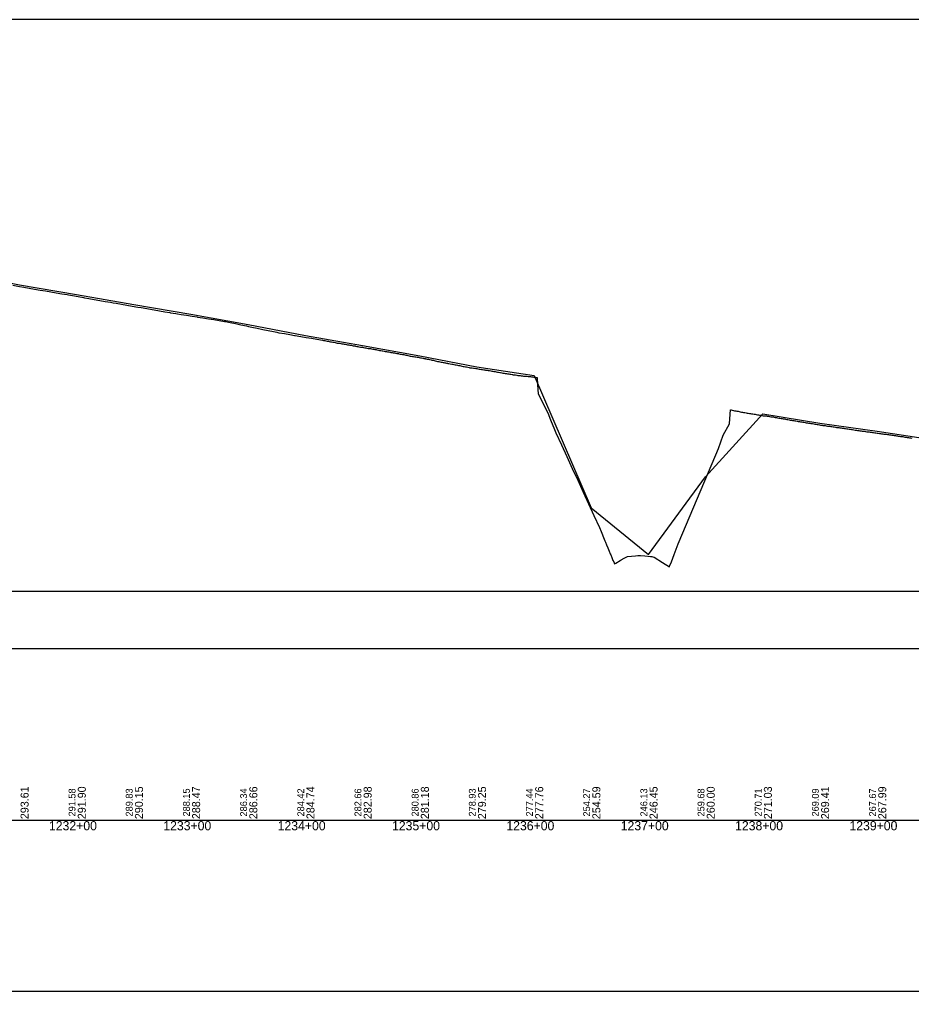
# Model space of a CAD drawing. Extents: x -3627 to 47473, y 2850 to 4350.
# Drawn here: x 10527 to 11307, y 2850 to 3700 of the extents above; entities that cross this region are included whole.
import ezdxf

# ---------------------------------------------------------------- set-up
doc = ezdxf.new("R2010")
doc.units = 0
for name, color, linetype in [('RD_DDB_Profile_EX', 7, 'Continuous'), ('RD_DDB_Profile_PR', 7, 'Continuous'), ('RD_DDB_StaTX', 7, 'Continuous'), ('RD_DDB_StripGrade', 7, 'Continuous'), ('RD_GPK_Profile_Cell', 7, 'Continuous'), ('RD_SHT_ShtClip', 7, 'Continuous')]:
    doc.layers.add(name, color=color, linetype=linetype)

msp = doc.modelspace()

# ---------------------------------------------------------------- linework, layer by layer
at = {"layer": 'RD_DDB_Profile_EX'}
for points in [[(10521.543546, 3467.5408), (10527.331218, 3466.473835), (10531.042498, 3465.8499), (10535.791975, 3465.048495), (10540.541451, 3464.24416), (10545.394843, 3463.41546), (10550.040404, 3462.623205), (10554.78988, 3461.81021), (10559.539357, 3460.99421), (10564.288833, 3460.1752), (10569.038309, 3459.353185), (10570.21671, 3459.14425), (10573.787786, 3458.523185), (10578.537262, 3457.694075), (10583.286738, 3456.86186), (10584.337263, 3456.67577), (10588.036215, 3456.02534), (10592.785691, 3455.18704), (10597.535167, 3454.345585), (10602.284644, 3453.50099), (10607.03412, 3452.65325), (10609.280141, 3452.25028), (10611.783596, 3451.824845), (10616.533073, 3451.014475), (10621.282549, 3450.200865), (10626.032025, 3449.384015), (10630.781502, 3448.563925), (10633.757415, 3448.048045), (10635.530978, 3447.7406), (10640.280455, 3446.91405)], [(10640.280455, 3446.91405), (10645.029931, 3446.084265), (10649.779407, 3445.251245), (10654.528884, 3444.414995), (10658.796669, 3443.65973), (10659.27836, 3443.58503), (10664.027836, 3442.845015), (10665.62232, 3442.5954), (10668.777313, 3442.09581), (10673.526789, 3441.341925), (10678.276265, 3440.58624), (10682.712889, 3439.86768), (10683.025742, 3439.817665), (10687.775218, 3439.057435), (10692.524694, 3438.296295), (10697.274171, 3437.53424), (10702.023647, 3436.771275), (10706.773123, 3436.007405), (10707.536259, 3435.87992), (10711.5226, 3435.037695), (10716.272076, 3434.033025), (10721.021552, 3433.02714), (10725.771029, 3432.020045), (10727.701013, 3431.648155), (10730.520505, 3431.05129), (10735.269982, 3430.04314), (10740.019458, 3429.03227), (10744.768934, 3428.01868), (10749.518411, 3427.00238), (10752.414609, 3426.418435), (10754.267887, 3426.09926), (10759.017363, 3425.277585), (10763.76684, 3424.452205), (10767.862399, 3423.713405), (10768.516316, 3423.602885), (10773.265792, 3422.797305), (10778.015269, 3421.98886), (10782.764745, 3421.17755), (10787.514221, 3420.36338), (10792.30311, 3419.57975), (10793.299339, 3419.285795), (10794.299228, 3419.14256), (10795.303154, 3418.943025), (10796.30302, 3418.74236), (10797.299199, 3418.58722), (10798.299138, 3418.43557), (10799.302349, 3418.18956), (10800.302281, 3417.99978), (10801.306182, 3417.80405), (10801.76265, 3417.758265), (10802.296945, 3417.704175), (10803.300912, 3417.483735), (10804.300165, 3417.34362), (10805.299063, 3417.053465), (10806.512127, 3416.93618), (10807.293775, 3416.84868), (10808.296695, 3416.689405), (10809.295635, 3416.499), (10810.299296, 3416.34801), (10811.289227, 3416.143485), (10812.292583, 3415.98803), (10813.291601, 3415.792745), (10814.293861, 3415.587365), (10815.29287, 3415.44605), (10816.287852, 3415.238785), (10817.285493, 3415.13517), (10818.288555, 3414.937095), (10819.28689, 3414.698905), (10820.236153, 3414.553075), (10820.760556, 3414.47179), (10821.232904, 3414.39124), (10822.230999, 3414.144775), (10823.222926, 3413.95443), (10824.221468, 3413.84666), (10825.510032, 3413.58003), (10826.221282, 3413.40868), (10827.21984, 3413.303775), (10828.219735, 3413.15324), (10829.225637, 3413.00416), (10830.259509, 3412.83919), (10831.2229, 3412.652015), (10832.215968, 3412.415745), (10833.215832, 3412.255615), (10834.221707, 3412.15596), (10835.214283, 3411.920275), (10836.219608, 3411.81587), (10837.219989, 3411.568015), (10838.218037, 3411.41629), (10839.217698, 3411.3046), (10839.758461, 3411.168325), (10840.215748, 3411.061815), (10841.215574, 3410.736265), (10842.215949, 3410.633465), (10843.213991, 3410.562915), (10844.507938, 3410.30062), (10845.219663, 3410.122675), (10846.212225, 3410.01766), (10847.217354, 3409.7752), (10848.209908, 3409.6658), (10849.257414, 3409.500895), (10850.215579, 3409.36089)], [(10850.215579, 3409.36089), (10851.208125, 3409.159955), (10852.213972, 3408.91263), (10853.213797, 3408.772075), (10854.211838, 3408.60583), (10855.211503, 3408.364145), (10856.204026, 3408.26264), (10857.209885, 3408.002185), (10858.20972, 3407.852405), (10858.756367, 3407.768325), (10859.207769, 3407.69868), (10860.208089, 3407.40217), (10861.213499, 3407.253535), (10862.20598, 3407.097785), (10863.505843, 3406.92422), (10864.203749, 3406.789215), (10865.204045, 3406.55249), (10865.999784, 3406.4476), (10867.057171, 3406.27399), (10868.255319, 3405.95116), (10868.979874, 3405.71299), (10869.981382, 3405.658365), (10871.057632, 3405.35229), (10871.977767, 3405.263525), (10873.061131, 3405.10046), (10874.065337, 3404.92293), (10874.981471, 3404.696475), (10876.064321, 3404.638615), (10876.977635, 3404.367665), (10877.972417, 3404.16866), (10878.973787, 3404.00678), (10880.062261, 3403.752835), (10880.970699, 3403.61878), (10881.972038, 3403.456255), (10882.503748, 3403.269245), (10883.063689, 3403.10206), (10883.968386, 3402.96807), (10885.061111, 3402.83864), (10885.96452, 3402.56961), (10887.253225, 3402.341515), (10887.960651, 3402.205725), (10889.056201, 3401.975375), (10889.957593, 3401.70641), (10890.958873, 3401.541925), (10892.055873, 3401.23155), (10892.955822, 3401.05243), (10893.95595, 3400.855115), (10895.057622, 3400.63565), (10896.05179, 3400.43008), (10896.953578, 3400.25052), (10897.954863, 3400.090495), (10898.43082, 3400), (10899.200461, 3399.766405), (10899.980789, 3399.649735), (10900.756284, 3399.49272), (10901.537873, 3399.37586), (10901.947913, 3399.288625), (10902.942719, 3399.16792), (10903.944035, 3398.882175), (10905.321318, 3398.572545), (10906.289417, 3398.434385), (10907.285695, 3398.18517), (10908.286228, 3397.993515), (10909.290089, 3397.890085), (10910.286909, 3397.696015), (10911.286863, 3397.4883), (10912.291126, 3397.30064), (10913.287248, 3397.09546), (10914.287728, 3396.80391), (10915.283841, 3396.615925), (10915.750083, 3396.570505), (10916.288006, 3396.487835), (10917.287768, 3396.25202), (10918.284402, 3396.145925), (10919.287844, 3395.95293), (10920.499559, 3395.674865), (10921.284159, 3395.517355), (10922.288121, 3395.367915), (10923.279311, 3395.25027), (10924.284325, 3395.157155), (10925.287587, 3395.00146), (10926.279366, 3394.83922), (10927.283602, 3394.65242), (10928.287439, 3394.49617), (10929.283221, 3394.31484), (10930.282738, 3394.12304), (10931.286477, 3393.97289), (10932.282174, 3393.80914), (10933.282317, 3393.710355), (10934.278008, 3393.50955), (10934.747988, 3393.46299), (10935.281708, 3393.402845), (10936.281067, 3393.24738), (10937.277375, 3393.059105), (10938.280349, 3392.921685), (10939.497465, 3392.70068), (10940.275954, 3392.490415), (10941.279549, 3392.426855), (10942.271456, 3392.23316), (10943.275053, 3392.08234), (10944.277978, 3391.956635)], [(10944.277978, 3391.956635), (10945.27047, 3391.68115), (10946.273334, 3391.574015), (10947.276886, 3391.422945), (10948.125354, 3391.223745), (10949.124194, 3391.036385), (10950.122287, 3390.855175), (10951.148796, 3390.59418), (10952.148343, 3390.44546), (10953.142979, 3390.32913), (10954.142482, 3390.09315), (10955.141247, 3389.994275), (10956.140658, 3389.875385), (10957.148192, 3389.713985), (10958.147617, 3389.57145), (10958.49537, 3389.501975), (10959.146274, 3389.372215), (10960.145539, 3389.265875), (10961.139915, 3389.1315), (10962.146749, 3388.939905), (10963.244846, 3388.77369), (10964.145717, 3388.676975), (10965.14415, 3388.54154), (10966.143276, 3388.39177), (10967.149238, 3388.26466), (10968.148342, 3388.222045), (10969.146607, 3388.136565), (10970.142673, 3388.010195), (10971.140938, 3387.99669), (10972.147425, 3387.81277), (10973.145623, 3387.75551), (10974.14443, 3387.69941), (10975.142528, 3387.48992), (10976.142609, 3387.381435), (10977.148226, 3387.203235), (10977.493275, 3387.1688), (10978.142782, 3387.104045), (10979.140709, 3387.06081), (10979.998327, 3387.024545), (10980.478464, 3380.58499), (10980.995674, 3372.54904), (10982.242752, 3370.042175), (10986.992228, 3360.49365), (10989.273855, 3355.906035), (10991.741705, 3349.777605), (10995.093873, 3341.451325), (10996.491181, 3338.414105), (11001.240657, 3328.08981), (11005.990134, 3317.764805), (11010.73961, 3307.439125), (11015.489086, 3297.112795), (11020.238563, 3286.78585), (11024.988039, 3276.45831), (11029.737515, 3266.130215), (11034.486992, 3255.801585), (11036.158402, 3252.166615), (11038.785117, 3245.509115), (11039.236468, 3244.248405), (11039.723685, 3242.888265), (11040.757161, 3240.529295), (11041.868532, 3238.03651), (11043.09915, 3235.14413), (11043.985944, 3232.84878), (11044.353961, 3231.89664), (11045.337396, 3229.568125), (11046.313644, 3226.949935), (11046.96272, 3225.75562), (11047.750403, 3224.08031), (11048.735421, 3224.659325), (11052.713079, 3226.998465), (11053.484897, 3227.4145), (11056.083854, 3228.815255), (11058.928951, 3230.36871), (11062.518094, 3230.696995), (11066.057082, 3231.0213), (11068.206228, 3231.208645), (11070.404375, 3231.419235), (11074.150154, 3230.998715), (11079.0208, 3230.45052), (11080.237702, 3230.313655), (11081.180516, 3230.20771), (11082.440301, 3229.869885), (11089.630611, 3225.29527), (11095.721485, 3221.48838), (11096.089507, 3222.43014), (11097.446264, 3225.824595), (11098.664693, 3229.068585), (11099.788999, 3232.04427), (11103.424789, 3241.514595), (11104.174874, 3243.540475), (11138.549471, 3324.95213), (11142.802066, 3336.407525), (11148.165449, 3346.339715), (11148.874291, 3354.928305), (11149.230024, 3358.743785), (11149.561851, 3358.646965), (11150.691356, 3358.433315), (11151.690668, 3358.183495), (11152.693441, 3357.896705), (11153.684135, 3357.706675), (11154.688151, 3357.576625)], [(11154.688151, 3357.576625), (11155.687467, 3357.39685), (11156.689704, 3357.240055), (11157.684389, 3356.89625), (11158.684944, 3356.64655), (11159.687186, 3356.533165), (11160.553298, 3356.35998), (11161.682409, 3356.24625), (11162.681208, 3356.009885), (11163.551638, 3355.83608), (11164.678636, 3355.676225), (11165.678671, 3355.50288), (11166.681439, 3355.372405), (11167.548557, 3355.24261), (11168.675414, 3355.015495), (11169.675456, 3354.92924), (11170.546896, 3354.79856), (11171.672856, 3354.51505), (11172.671673, 3354.315525), (11173.675664, 3354.26531), (11174.543814, 3354.048455), (11175.669112, 3353.95206), (11176.668449, 3353.71309), (11177.672436, 3353.45219), (11178.540733, 3353.495895), (11178.863948, 3353.479455), (11179.71095, 3353.30824), (11180.568666, 3353.265185), (11181.303162, 3353.11465), (11182.307317, 3353.01467), (11183.298534, 3352.7), (11184.301413, 3352.585265), (11185.305571, 3352.49262), (11186.304188, 3352.4), (11187.300959, 3352.170315), (11188.299591, 3352.027495), (11189.301702, 3351.88496), (11190.298487, 3351.785035), (11191.297115, 3351.492435), (11192.301285, 3351.362105), (11193.299912, 3351.15), (11194.295396, 3351.05), (11195.299569, 3350.84237), (11196.298201, 3350.634565), (11197.301037, 3350.484555), (11198.292897, 3350.32665), (11199.295725, 3350.18442), (11200.299907, 3349.942195), (11201.298534, 3349.718415), (11202.387926, 3349.57648), (11203.388252, 3349.37625), (11204.390252, 3349.31841), (11205.393751, 3349.152665), (11206.386102, 3348.902535), (11207.38869, 3348.73425), (11208.389038, 3348.568185), (11209.392536, 3348.426165), (11210.386531, 3348.23426), (11211.386894, 3348.034105), (11212.39039, 3347.88412), (11213.381839, 3347.760325), (11214.385333, 3347.55244), (11215.388825, 3347.41041), (11216.387705, 3347.252075), (11217.38318, 3347.068315), (11218.383597, 3346.90999), (11219.385564, 3346.76807), (11220.229469, 3346.6), (11220.870179, 3346.56812), (11221.869667, 3346.367795), (11222.867744, 3346.17563), (11223.867242, 3345.97538), (11224.866753, 3345.866835), (11225.864811, 3345.69982), (11226.865155, 3345.51628), (11227.864696, 3345.38297), (11228.866784, 3345.224505), (11229.866321, 3345.07425), (11230.865871, 3344.906645), (11231.8639, 3344.815015), (11232.863462, 3344.60583), (11233.871105, 3344.432075), (11234.869105, 3344.33192), (11235.868687, 3344.222615), (11236.868283, 3344.08156), (11237.870234, 3343.940795), (11238.869826, 3343.790705), (11239.870342, 3343.690635), (11240.868312, 3343.53111), (11241.867936, 3343.34046), (11242.827964, 3343.15), (11243.828254, 3343.059665), (11244.826916, 3342.880555), (11245.825578, 3342.8), (11246.82424, 3342.60984), (11247.826118, 3342.5), (11248.826444, 3342.320305), (11249.825104, 3342.190045), (11250.823764, 3342.05), (11251.822424, 3341.91007), (11252.821083, 3341.779745)], [(11252.821083, 3341.779745), (11253.828223, 3341.620525), (11254.826883, 3341.46032), (11255.824439, 3341.35), (11256.827306, 3341.2), (11258.271562, 3340.989525), (11259.271035, 3340.8), (11260.270507, 3340.66059), (11261.26998, 3340.489355), (11262.269452, 3340.35), (11263.270981, 3340.23922), (11264.269672, 3340.06741), (11265.269152, 3340.01092), (11266.268631, 3339.88902), (11267.275539, 3339.738905), (11268.275008, 3339.55), (11269.276617, 3339.47754), (11270.276097, 3339.37742), (11271.275576, 3339.2), (11272.274219, 3339.05), (11273.273695, 3338.95), (11274.275377, 3338.761565), (11275.274863, 3338.65), (11276.27435, 3338.45), (11277.273836, 3338.338255), (11278.273322, 3338.2764), (11279.275079, 3338.01188), (11280.281852, 3337.87399), (11281.280458, 3337.786245), (11282.27994, 3337.66214), (11283.282189, 3337.47578), (11284.283994, 3337.375625), (11285.283483, 3337.313265), (11286.287691, 3337.11297), (11287.28631, 3336.97514), (11288.288215, 3336.8), (11289.286832, 3336.662205), (11290.287873, 3336.51271), (11291.28648, 3336.4256), (11292.28847, 3336.28712), (11293.296682, 3336.1), (11294.295269, 3335.91314), (11295.296387, 3335.786745), (11295.706357, 3335.75), (11296.702402, 3335.56321), (11297.70228, 3335.439975), (11298.705759, 3335.31335), (11299.70462, 3335.2), (11300.704521, 3334.963525), (11301.705629, 3334.827065), (11302.699162, 3334.72718), (11303.70159, 3334.55), (11304.701506, 3334.45), (11305.701441, 3334.2914), (11306.702497, 3334.127615), (11307.703786, 3333.95557)]]:
    msp.add_lwpolyline(points, dxfattribs=at)
at = {"layer": 'RD_DDB_Profile_PR'}
msp.add_lwpolyline([(10477.33, 3477.7505), (10527.33, 3468.074), (10577.33, 3459.505), (10627.33, 3450.76), (10677.33, 3442.337), (10727.33, 3433.3195), (10777.33, 3423.7055), (10827.33, 3414.887), (10877.33, 3405.897), (10927.33, 3396.245), (10977.33, 3388.785), (11027.33, 3272.9655), (11077.33, 3232.241), (11127.33, 3299.9805), (11177.33, 3355.141), (11227.33, 3347.0545), (11277.33, 3339.935), (11327.33, 3332.497)], dxfattribs=at)
at = {"layer": 'RD_GPK_Profile_Cell'}
msp.add_line((1000, 3000), (46705.077602, 3000), dxfattribs=at)
at = {"layer": 'RD_SHT_ShtClip'}
for points in [[(11500.165, 3200), (11500.165, 3700), (11500.165, 3700), (10000.33, 3700), (10000.33, 3200)], [(9980.33, 3150), (11520, 3150), (11520, 2850), (9980.33, 2850)]]:
    msp.add_lwpolyline(points, close=True, dxfattribs=at)

# ---------------------------------------------------------------- texts
at = {"layer": 'RD_DDB_StaTX'}
for s, p in [('1232+00', (10553.125471, 2991)), ('1233+00', (10653.125471, 2991)), ('1234+00', (10753.125471, 2991)), ('1235+00', (10853.125471, 2991)), ('1236+00', (10953.125471, 2991)), ('1237+00', (11053.125471, 2991)), ('1238+00', (11153.125471, 2991)), ('1239+00', (11253.125471, 2991))]:
    msp.add_text(s, height=8, dxfattribs=at).set_placement(p)
at = {"layer": 'RD_DDB_StripGrade'}
for s, height, p in [('293.61', 7, (10535.33, 3000.75)), ('291.58', 6, (10576.33, 3003.073688)), ('291.90', 7, (10585.33, 3000.75)), ('289.83', 6, (10626.33, 3003.073688)), ('290.15', 7, (10635.33, 3000.75)), ('288.15', 6, (10676.33, 3003.073688)), ('288.47', 7, (10685.33, 3000.75)), ('286.34', 6, (10726.33, 3003.073688)), ('286.66', 7, (10735.33, 3000.75)), ('284.42', 6, (10776.33, 3003.073688)), ('284.74', 7, (10785.33, 3000.75)), ('282.66', 6, (10826.33, 3003.073688)), ('282.98', 7, (10835.33, 3000.75)), ('280.86', 6, (10876.33, 3003.073688)), ('281.18', 7, (10885.33, 3000.75)), ('278.93', 6, (10926.33, 3003.073688)), ('279.25', 7, (10935.33, 3000.75)), ('277.44', 6, (10976.33, 3003.073688)), ('277.76', 7, (10985.33, 3000.75)), ('254.27', 6, (11026.33, 3003.073688)), ('254.59', 7, (11035.33, 3000.75)), ('246.13', 6, (11076.33, 3003.073688)), ('246.45', 7, (11085.33, 3000.75)), ('259.68', 6, (11126.33, 3003.073688)), ('260.00', 7, (11135.33, 3000.75)), ('270.71', 6, (11176.33, 3003.073688)), ('271.03', 7, (11185.33, 3000.75)), ('269.09', 6, (11226.33, 3003.073688)), ('269.41', 7, (11235.33, 3000.75)), ('267.67', 6, (11276.33, 3003.073688)), ('267.99', 7, (11285.33, 3000.75))]:
    msp.add_text(s, height=height, rotation=90, dxfattribs=at).set_placement(p)

doc.saveas('drawing.dxf')
